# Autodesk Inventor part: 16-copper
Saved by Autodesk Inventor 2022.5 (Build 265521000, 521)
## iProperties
Created: 2024-07
Part Number: 16-copper
Material: Generic
Document SubType Name: Modeling
Designer: AdminForWorker
Density: 1 g/cm^3
Appearance: Default
Title: 16-copper
Author: AdminForWorker
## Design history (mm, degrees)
feature "Body1"
feature "Body3"
feature "Body2"
body "Solid1"
body "Solid2"
body "Solid3"
